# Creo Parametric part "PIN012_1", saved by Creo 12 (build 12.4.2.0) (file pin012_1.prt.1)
Units: Custom; MM, KILOGRAM, SECS

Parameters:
  PTC_WM_ITERATION = "0"
  PTC_WM_VERSION = "-.0"
  PTC_WM_LIFECYCLE_STATE = "In Work"
  PTC_WM_LIFECYCLE = "MO_CADDocument"
  PTC_WM_CREATED_BY = "Maximilian Roepper (Z0017RMS: MO)"
  PTC_WM_CREATED_ON = "18-Sep-26 11:36:42 AM"
  PTC_WM_MODIFIED_BY = "Maximilian Roepper (Z0017RMS: MO)"
  PTC_WM_MODIFIED_ON = "18-Sep-26 11:36:46 AM"
  PDMLINKNUMBER = "PDM000071455019"
  PTC_WM_NAME = "pin012_1.prt"
  PTC_WM_NUMBER = "PDM000071455019"

Other parameters: WEIGHT, WEIGHT_FACTOR, WEIGHT_ADD, _MASS_TEMP, _DIFF_TEMP, MC_ERRORS, SUPPLIER

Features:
  1. coordinate system
  2. datum plane "PRT_YZ"
  3. datum plane "PRT_XY"
  4. datum plane "PRT_XZ"
  5. coordinate system
  6. datum axis
  7. datum axis
  8. datum axis
  9. coordinate system
  10. imported feature

Other named items: PRT, SIEMENS_MO, DRW_VIEW_ORG, PRT_X, PRT_Y, PRT_Z, CS0, ROUGH_GROB

Layers: 00_STD_CSYS-KSYS, 01_STD_PLANES-EBENEN, 02_STD_AXES-ACHSEN, 03_STD_CSYS-KSYS, 24_IMPORT_FEAT-IMPORT_KE

Surfaces: 14 plane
